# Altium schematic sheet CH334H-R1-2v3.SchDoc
size 209 x 148 mm; PageSetup: Record=PageOptions¦CenterHorizontal=True¦CenterVertical=True¦PrintScale=0.65¦XCorrection=1.00¦YCorrection=1.00¦PrintKind=1¦BorderSize=5000000¦LeftOffset=0¦BottomOffset=0¦Orientation=2¦PaperLength=1000¦PaperWidth=1000¦Scale=100¦PaperSource=7¦PrintQuality=-4¦MediaType=1¦DitherType=10¦PaperKind=16 开 195x270¦PrintScaleMode=1
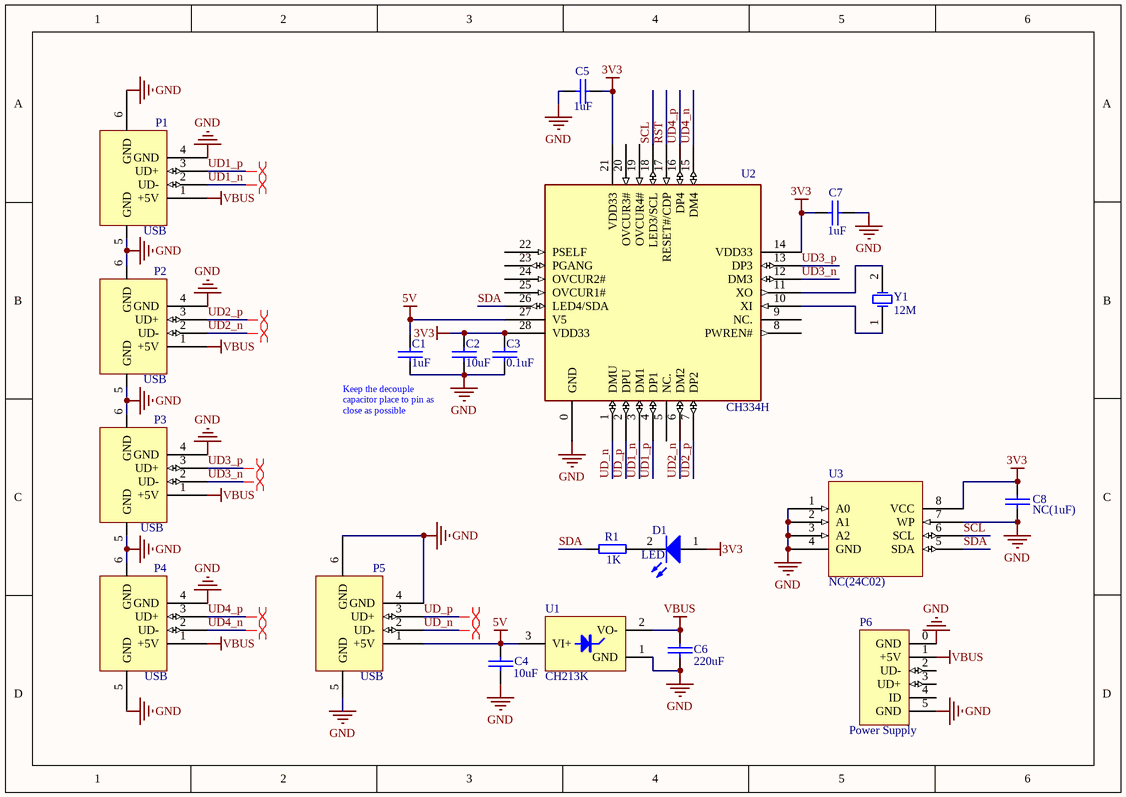
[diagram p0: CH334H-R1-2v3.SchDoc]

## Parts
C1  1uF  [0603_C]
C2  10uF  [0603_C]
C3  0.1uF  [0603_C]
C4  10uF  [0603_C]
C5  1uF  [0603_C]
C6  220uF  [CD0.1]
C7  1uF  [0603_C]
C8  NC(1uF)  [0603_C]
D1  LED  [0603+]
P1  USB  [USBAF]
P2  USB  [USB2.0-A-F-TH_4P-V_13.7mm]
P3  USB  [USB2.0-A-F-TH_4P-V_13.7mm]
P4  USB  [USB2.0-A-F-TH_4P-V_13.7mm]
P5  USB  [USBAF]
P6  Power Supply  [USBMICROB-02-GXPX-A1T2]
R1  1K  [0603_R]
U1  CH213K  [SOT-23-3]
U2  CH334H  [QFN28_5X5]
U3  NC(24C02)  [SOIC-8_150mil]
Y1  12M  [XT_AT49]

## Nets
3V3: C2.1 C3.1 C5.1 C7.2 C8.2 D1.1(A) U2.14(VDD33) U2.21(VDD33) U2.28(VDD33) U3.8(VCC)
5V: C1.1 C4.1 P5.1(+5V) U1.3(VI+) U2.27(V5)
GND: C1.2 C2.2 C3.2 C4.2 C5.2 C6.2 C7.1 C8.1 P1.4(GND) P1.5(GND) P1.6(GND) P2.4(GND) P2.5(GND) P2.6(GND) P3.4(GND) P3.5(GND) P3.6(GND) P4.4(GND) P4.5(GND) P4.6(GND) P5.4(GND) P5.5(GND) P5.6(GND) P6.0(GND) P6.5(GND) U1.1(GND) U2.0(GND) U3.1(A0) U3.2(A1) U3.3(A2) U3.4(GND) U3.7(WP)
VBUS: C6.1 P1.1(+5V) P2.1(+5V) P3.1(+5V) P4.1(+5V) P6.1(+5V) U1.2(VO-)
RST: U2.17(RESET#/CDP)
SCL: U2.18(LED3/SCL) U3.6(SCL)
SDA: R1.1 U2.26(LED4/SDA) U3.5(SDA)
UD1_n: P1.2(UD-) U2.3(DM1)
UD1_p: P1.3(UD+) U2.4(DP1)
UD2_n: P2.2(UD-) U2.6(DM2)
UD2_p: P2.3(UD+) U2.7(DP2)
UD3_n: P3.2(UD-) U2.12(DM3)
UD3_p: P3.3(UD+) U2.13(DP3)
UD4_n: P4.2(UD-) U2.15(DM4)
UD4_p: P4.3(UD+) U2.16(DP4)
UD_n: P5.2(UD-) U2.1(DMU)
UD_p: P5.3(UD+) U2.2(DPU)
NetD1_2: D1.2(K) R1.2
NetU2_10: U2.10(XI) Y1.1(OSC1)
NetU2_11: U2.11(XO) Y1.2(OSC2)

Not connected (* = marked no-connect by the designer): P6 2(UD-) 3(UD+) 4(ID); U2 5(NC.) 8(PWREN#) 9(NC.) 19(OVCUR4#) 20(OVCUR3#) 22(PSELF) 23(PGANG) 24(OVCUR2#) 25(OVCUR1#)

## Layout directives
differential pair: UD1_n, UD1_p, UD2_n, UD2_p, UD3_n, UD3_p, UD4_n, UD4_p, UD_n, UD_p

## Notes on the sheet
- Keep the decouple capacitor place to pin as close as possible

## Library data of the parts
C1-C8 = CAP: Capacitor
D1 = LED: Typical INFRARED GaAs LED
P1-P5 = USB: USB Port
P6 = MicroUSB: MicroUSB Port
R1 = RES
U1 = CH213K: Ideal Diode 5V*1A
U2 = CH334H: 4 ports High-Speed USB MTT Hub with 4 over current detect
U3 = 24C01
Y1 = XTAL: Crystal Oscillator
